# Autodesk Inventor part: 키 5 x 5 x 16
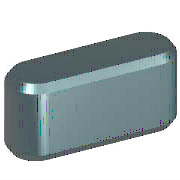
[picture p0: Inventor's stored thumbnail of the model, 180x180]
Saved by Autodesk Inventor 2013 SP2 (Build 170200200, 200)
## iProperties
IsCustomPart: 1
Created: 2012-02
Part Number: 키 5 x 5 x 16
Material: 강철, 연강
Description: 키 및 해당 키홈
Document SubType Name: Modeling
Standard: KS B 1311
Designer: mduedu
Standards Organization: KS
Language: ko-KR
Size Designation: 5 x 5 x 16
Categories: <MemberInstance><Categories><Category DisplayName="샤프트 부품" InternalName="7f7aeb1f-a693-4053-b835-cee3144e0d98" Mnemonic="SHFT"><Category DisplayName="키" Interna
Density: 1 g/cm^3
Author: mduedu
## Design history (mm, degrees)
workplane "Work Plane1"
workplane "Work Plane2"
sketch "스케치1"
  geometry: L1 (2.5, 2.5)-(11.5, 2.5); L2 (11.5, -2.5)-(2.5, -2.5); L3 (0, 8.9)-(0, -4.4) reference; L4 (-3.2, 0)-(19.2, 0) reference; L5 (14, 0)-(14, 7); A1 r 2.5 centre (2.5, 0) between (2.5, 2.5) and (2.5, -2.5); A2 r 2.5 centre (11.5, 0) between (11.5, -2.5) and (11.5, 2.5)
  constraints: 6 end point, 5 point on circle, 4 tangent, 3 point on line, 2 centre point, 1 horizontal, 1 parallel, 1 perpendicular
  dimensions: "d0" = 2.5 radius of A1 (= 0.5 x PB); "d13" = 2.5 radius of A2 (= 0.5 x PB); "d14" = 14 distance between parallel lines of L5 L3 (= NLG)
extrude "본체1" new body sketch "스케치1" taper "d3" = 0 deg; stored distance "d4" = 10
workplane "Work Plane3"
body "Solid1"
chamfer "모따기1" distance "d8" = 0.4 (= PHH); stored, may be unused: second distance "d9" = 0.4 (= PHH), angle "d15" = 45 deg
other parameters: "d1" = -3 (= -PNT), "d2" = 2 (= PH - PNT), "NLG" = 14 [user parameter; used in 3 equation terms], "PB" = 5 [user parameter; used in 2 equation terms], "PNT" = 3 [user parameter; used in 2 equation terms], "PH" = 5 [user parameter; used in 1 equation term], "PHH" = 0.4 [user parameter; used in 2 equation terms], "d10" = 0, "d16" = 0, "d17" = 0, "d18" = 0, "WDMIN" = 12 [user parameter], "PLB2" = 14 (= NLG) [user parameter], "WDMAX" = 17 [user parameter], "PLB1" = 14 (= NLG) [user parameter], "RR" = 0.16 [user parameter], "PUEB" = 2.3 [user parameter]
